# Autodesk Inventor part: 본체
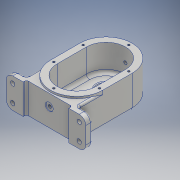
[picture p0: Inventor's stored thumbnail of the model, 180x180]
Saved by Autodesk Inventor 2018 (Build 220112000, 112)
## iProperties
Created: 2021-05
Part Number: 본체
Material: 알루미늄 6061
Document SubType Name: Modeling
Designer: Admin
Density: 2.7 g/cm^3
Appearance: 알루미늄 - 평지
Mass: 756.275 g
Surface Area: 582.942 cm^2
Volume: 280.102 cm^3
Author: Admin
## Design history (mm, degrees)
sketch "스케치1"
  geometry: L1 (-56, 0)-(56, 0) reference; L2 (0, -87.5)-(0, 87.5) reference; L3 (0, 22.5)-(0, -22.5); L4 (-40, 22.5)-(-40, -22.5); L5 (40, -22.5)-(40, 22.5); A1 r 40 centre (0, 22.5) between (40, 22.5) and (-40, 22.5); A2 r 40 centre (0, -22.5) between (-40, -22.5) and (40, -22.5); 2 further points
  constraints: 8 end point, 4 point on circle, 4 tangent, 2 centre point, 2 point on line, 1 coincident, 1 midpoint, 1 parallel
  dimensions: "d0" = 80 diameter of A2; "d1" = 45 distance of L5.start L5.end
extrude "돌출1" new body sketch "스케치1" distance "d2" = 49; taper "d3" = 0 deg
node "작업 평면1"
sketch "스케치2"
  geometry: L1 (61, -3)-(-61, -3); L2 (-61, -3)-(-61, -49); L3 (-61, -49)-(61, -49); L4 (61, -49)-(61, -3); L5 (-40, -49)-(40, -49) reference; L6 (85.4, 0)-(-85.4, 0) reference; L7 (0, -58.8)-(0, 9.8) reference; L8 (40, 0)-(-40, 0) reference; 2 further points
  constraints: 8 end point, 2 midpoint, 2 parallel, 1 horizontal, 1 perpendicular, 1 other
  dimensions: "d5" = 46 distance of L3.end L1.start; "d6" = 122 distance of L1.start L1.end
extrude "돌출2" join sketch "스케치2" distance "d7" = 10; taper "d8" = 0 deg
sketch "스케치3"
  geometry: L1 (-61, 3)-(61, 3) reference; L2 (-61, 49)-(-61, 3) reference; L3 (61, 49)-(-61, 49) reference; L4 (61, 3)-(61, 49) reference; L5 (0, 58.8)-(0, -9.8) reference; L6 (61, 49)-(-61, 49) reference; L7 (-40, 3)-(40, 3); L8 (40, 3)-(40, 49); L9 (40, 49)-(-40, 49); L10 (-40, 49)-(-40, 3); 1 further point
  constraints: 8 end point, 2 parallel, 2 point on line, 1 horizontal, 1 perpendicular, 1 other
  dimensions: "d9" = 80 distance between parallel lines of L8 L10
extrude "돌출3" join sketch "스케치3" distance "d10" = 37; taper "d11" = 0 deg
sketch "스케치4"
  geometry: L1 (-40, 22.5)-(-40, -22.5) reference; L2 (40, -22.5)-(40, 22.5) reference; L3 (0, 22.5)-(0, -22.5); L4 (-30, 22.5)-(-30, -22.5); L5 (30, -22.5)-(30, 22.5); A1 r 40 centre (0, -22.5) between (-40, -22.5) and (40, -22.5) reference; A2 r 40 centre (0, 22.5) between (40, 22.5) and (-40, 22.5) reference; A3 r 30 centre (0, 22.5) between (30, 22.5) and (-30, 22.5); A4 r 30 centre (0, -22.5) between (-30, -22.5) and (30, -22.5); 2 further points
  constraints: 8 end point, 4 point on circle, 4 tangent, 2 centre point, 1 midpoint, 1 parallel, 1 vertical
  dimensions: "d12" = 60 diameter of A4
extrude "돌출4" cut sketch "스케치4" distance "d13" = 41; taper "d14" = 0 deg
sketch "스케치5"
  geometry: L1 (-30, -22.5)-(-30, 22.5) reference; L2 (30, 22.5)-(30, -22.5) reference; C1 r 14 at (0, 22.5); C2 r 14 at (0, -22.5); A1 r 30 centre (0, -22.5) between (-30, -22.5) and (30, -22.5) reference; A2 r 30 centre (0, 22.5) between (30, 22.5) and (-30, 22.5) reference; 1 further point
  constraints: 2 centre point, 2 coincident
  dimensions: "d15" = 28 diameter of C1; "d16" = 28 diameter of C2
  node "투영된 루프3"
sketch "스케치6"
  geometry: L1 (40, -59.5)-(40, 22.5) reference; L2 (-40, 22.5)-(-40, -59.5) reference; L3 (-61, -59.5)-(-40, -59.5) reference; L4 (-61, -69.5)-(-61, -59.5) reference; L5 (-61, -69.5)-(61, -69.5) reference; L6 (61, -69.5)-(61, -59.5) reference; L7 (40, -59.5)-(61, -59.5) reference; L8 (85.4, 0)-(-85.4, 0) reference; L9 (0, -95.9)-(0, 88.9) reference; L10 (0, 22.5)-(0, -22.5); L11 (26, -22.5)-(26, -7.5); L12 (-26, -7.5)-(26, -7.5); L13 (-26, -7.5)-(-26, -22.5); A1 r 40 centre (0, 22.5) between (40, 22.5) and (-40, 22.5) reference; A2 r 26 centre (0, -22.5) between (-26, -22.5) and (26, -22.5); 2 further points
  constraints: 10 end point, 2 point on circle, 2 point on line, 2 tangent, 1 centre point, 1 coincident, 1 horizontal, 1 midpoint, 1 parallel
  dimensions: "d17" = 52 diameter of A2; "d19" = 30 distance from line of L12 A1.centre; "d20" = 47 distance from line of L5 L10.end; "d21" = 15 distance of L12.start L13.end
extrude "돌출5" join sketch "스케치6" distance "d22" = 11; taper "d23" = 0 deg
sketch "스케치7"
  geometry: L1 (-26, -22.5)-(-26, -7.5) reference; L2 (-26, -7.5)-(26, -7.5) reference; L3 (26, -7.5)-(26, -22.5) reference; L4 (40, -59.5)-(40, 22.5) reference; L5 (-40, 22.5)-(-40, -59.5) reference; L6 (-61, -59.5)-(-40, -59.5) reference; L7 (-61, -69.5)-(-61, -59.5) reference; L8 (-61, -69.5)-(61, -69.5) reference; L9 (61, -69.5)-(61, -59.5) reference; L10 (40, -59.5)-(61, -59.5) reference; L11 (85.4, 0)-(-85.4, 0) reference; L12 (0, -95.9)-(0, 88.9) reference; L13 (0, 22.5)-(0, -22.5); L14 (-26, 22.5)-(-26, -22.5); L15 (26, -22.5)-(26, 22.5); A1 r 26 centre (0, -22.5) between (-26, -22.5) and (26, -22.5) reference; A2 r 40 centre (0, 22.5) between (40, 22.5) and (-40, 22.5) reference; A3 r 26 centre (0, 22.5) between (26, 22.5) and (-26, 22.5); A4 r 26 centre (0, -22.5) between (-26, -22.5) and (26, -22.5); 2 further points
  constraints: 8 end point, 4 point on circle, 4 tangent, 2 centre point, 1 collinear, 1 midpoint, 1 parallel
  dimensions: "d24" = 52 diameter of A4
extrude "돌출6" join sketch "스케치7" distance "d25" = 8; taper "d26" = 0 deg
extrude "돌출7" cut sketch "스케치5" distance "d27" = 8; taper "d28" = 0 deg
sketch "스케치8"
  geometry: L1 (26, -7.5)-(-26, -7.5) reference; L2 (26, -7.5)-(26, 22.5) reference; L3 (-26, 22.5)-(-26, -7.5) reference; C1 r 14 at (0, 22.5); A1 r 26 centre (0, 22.5) between (26, 22.5) and (-26, 22.5) reference; 1 further point
  constraints: 1 centre point, 1 coincident
  dimensions: "d29" = 28 diameter of C1
extrude "돌출8" cut sketch "스케치8" distance "d30" = 4; taper "d31" = 0 deg
sketch "스케치9"
  geometry: C1 r 14 at (0, 0) reference; C2 r 11 at (0, 0); 1 further point
  constraints: 1 centre point, 1 coincident
  dimensions: "d32" = 22 diameter of C2
extrude "돌출9" cut sketch "스케치9" stored distance "d33" = 4; taper "d34" = 0 deg
sketch "스케치10"
  geometry: C1 r 14 at (0, 0) reference; C2 r 10 at (0, 0); 1 further point
  constraints: 1 centre point, 1 coincident
  dimensions: "d35" = 20 diameter of C2
extrude "돌출10" cut sketch "스케치10" distance "d36" = 4; taper "d37" = 0 deg
node "작업 평면2"
sketch "스케치11"
  geometry: L1 (0, -72)-(0, 12) reference; L2 (40, 0)-(-40, 0) reference; C1 r 6 at (0, -21); 1 further point
  constraints: 1 centre point, 1 point on line
  dimensions: "d39" = 12 diameter of C1; "d40" = 21 distance from line of L2 C1.centre
extrude "돌출11" join sketch "스케치11" stored distance "d41" = 4; taper "d42" = 0 deg
sketch "스케치12"
  geometry: L1 (-30, -22.5)-(-30, 22.5) reference; L2 (30, 22.5)-(30, -22.5) reference; L3 (-40, 22.5)-(-40, -22.5) reference; L4 (40, -22.5)-(40, 22.5) reference; L5 (-85.4, 0)-(85.4, 0) reference; L6 (0, -96.5)-(0, 92.5) reference; L7 (0, 22.5)-(0, -22.5); L8 (-35, 22.5)-(-35, -22.5); L9 (35, -22.5)-(35, 22.5); A1 r 30 centre (0, -22.5) between (-30, -22.5) and (30, -22.5) reference; A2 r 30 centre (0, 22.5) between (30, 22.5) and (-30, 22.5) reference; A3 r 40 centre (0, -22.5) between (-40, -22.5) and (40, -22.5) reference; A4 r 40 centre (0, 22.5) between (40, 22.5) and (-40, 22.5) reference; A5 r 35 centre (0, 22.5) between (35, 22.5) and (-35, 22.5); A6 r 35 centre (0, -22.5) between (-35, -22.5) and (35, -22.5); 8 further points
  constraints: 8 end point, 6 point on circle, 4 coincident, 4 tangent, 2 centre point, 1 collinear, 1 midpoint, 1 parallel
  dimensions: "d43" = 70 diameter of A6
hole "구멍1" sketch "스케치12" at (0, 57.5), (0, -57.5), (-35, 22.5), (35, 22.5), (35, -22.5), (-35, -22.5) diameter "d44" = 3.242; stored, may be unused: countersink angle "d48" = 90 deg, drill point angle "d50" = 118 deg; dims "d45" = 8, "d46" = 4, "d47" = 2, "d49" = 10
fillet "모깎기1" dims "d51" = 10, "d79" = 5, "d80" = 3, "d96" = 0.3
sketch "스케치13"
  geometry: L1 (-61, 39)-(-61, 13) reference; L2 (-51, 3)-(-40, 3) reference; L3 (-40, 3)-(-40, 49) reference; L4 (-40, 49)-(-51, 49) reference; L5 (51, 49)-(40, 49) reference; L6 (40, 49)-(40, 3) reference; L7 (40, 3)-(51, 3) reference; L8 (61, 13)-(61, 39) reference; C1 r 5.5 at (-51, 13); C2 r 5.5 at (-51, 39); C3 r 5.5 at (51, 13); C4 r 5.5 at (51, 39); A1 r 10 centre (-51, 39) between (-51, 49) and (-61, 39) reference; A2 r 10 centre (-51, 13) between (-61, 13) and (-51, 3) reference; A3 r 10 centre (51, 39) between (61, 39) and (51, 49) reference; A4 r 10 centre (51, 13) between (51, 3) and (61, 13) reference; 1 further point
  constraints: 4 centre point, 4 coincident
  dimensions: "d52" = 11 diameter of C1; "d53" = 11 diameter of C2; "d54" = 11 diameter of C3; "d55" = 11 diameter of C4
extrude "돌출12" cut sketch "스케치13" distance "d56" = 2; taper "d57" = 0 deg
sketch "스케치14"
  geometry: C1 r 5.5 at (0, 0) reference; C2 r 5.5 at (0, 26) reference; C3 r 5.5 at (102, 26) reference; C4 r 5.5 at (102, 0) reference; C5 r 3.3 at (0, 0); C6 r 3.3 at (0, 26); C7 r 3.3 at (102, 0); C8 r 3.3 at (102, 26); 1 further point
  constraints: 4 centre point, 4 coincident
  dimensions: "d58" = 6.6 diameter of C5; "d59" = 6.6 diameter of C6; "d60" = 6.6 diameter of C7; "d61" = 6.6 diameter of C8
extrude "돌출13" cut sketch "스케치14" stored distance "d62" = 0; taper "d63" = 0 deg
chamfer "모따기1" distance "d76" = 1; stored, may be unused: second distance "d77" = 2, angle "d78" = 45 deg
sketch "스케치18"
  geometry: L1 (0, -96.506)-(0, 92.534) reference; L2 (51, -62.5)-(51, -69.5) reference; L3 (43, -62.5)-(51, -62.5) reference; L4 (37, 22.5)-(37, -56.5) reference; L5 (-37, -56.5)-(-37, 22.5) reference; L6 (-51, -62.5)-(-43, -62.5) reference; L7 (-51, -69.5)-(-51, -62.5) reference; L8 (-51, -69.5)-(51, -69.5) reference; L9 (29, -22.5)-(29, 22.5) reference; L10 (-29, 22.5)-(-29, -22.5) reference; L11 (-51, -69.5)-(51, -69.5) reference; L12 (-35, -69.5)-(35, -69.5); L13 (35, -69.5)-(35, -64.5); L14 (35, -64.5)-(-35, -64.5); L15 (-35, -64.5)-(-35, -69.5); A1 r 37 centre (0, 22.5) between (37, 22.5) and (-37, 22.5) reference; A2 r 29 centre (0, -22.5) between (-29, -22.5) and (29, -22.5) reference; A3 r 29 centre (0, 22.5) between (29, 22.5) and (-29, 22.5) reference; A4 r 6 centre (43, -56.5) between (37, -56.5) and (43, -62.5) reference; A5 r 6 centre (-43, -56.5) between (-43, -62.5) and (-37, -56.5) reference; 1 further point
  constraints: 8 end point, 2 parallel, 1 horizontal, 1 perpendicular, 1 point on line, 1 other
  dimensions: "d81" = 5 distance between parallel lines of L12 L14; "d82" = 70 distance between parallel lines of L15 L13
extrude "돌출15" cut sketch "스케치18" stored distance "d83" = 1; taper "d84" = 0 deg
sketch "스케치19"
  geometry: L1 (0, 46)-(70, 46) reference; L2 (0, 0)-(0, 46) reference; L3 (70, 0)-(0, 0) reference; L4 (70, 0)-(70, 46) reference; L5 (75, 49)-(-5, 49) reference; L6 (35, -23)-(35, 61) reference; C1 r 6 at (35, 28); 1 further point
  constraints: 1 centre point, 1 point on line
  dimensions: "d85" = 12 diameter of C1; "d86" = 21 distance from line of L5 C1.centre
extrude "돌출16" cut sketch "스케치19" distance "d87" = 1; taper "d88" = 0 deg
sketch "스케치20"
  geometry: C1 r 6 at (0, 0) reference; 2 further points
  constraints: 1 coincident
hole "구멍3" sketch "스케치20" at (0, 0) diameter "d89" = 4.917; stored, may be unused: countersink angle "d93" = 90 deg, drill point angle "d95" = 118 deg; dims "d90" = 140, "d91" = 4, "d92" = 2, "d94" = 140
sketch "스케치21" dims "d97" = 40
  geometry: L1 (26, -7.5)-(-26, -7.5) reference; L2 (26, -7.5)-(26, 22.5) reference; L3 (-26, 22.5)-(-26, -7.5) reference; L4 (0, -96.506)-(0, 92.534) reference; C1 r 15 at (0, 22.5) reference; A1 r 26 centre (0, 22.5) between (26, 22.5) and (-26, 22.5) reference; 3 further points
  constraints: 1 coincident, 1 point on line, 1 vertical alignment, 2 other
hole "구멍4" sketch "스케치21" at (0, 42.5) diameter "d98" = 3.242; stored, may be unused: countersink angle "d102" = 90 deg, drill point angle "d104" = 118 deg; dims "d99" = 8, "d100" = 4, "d101" = 2, "d103" = 10
sketch "스케치22"
  geometry: L1 (0, -96.506)-(0, 92.534) reference; L2 (-51, -69.5)-(-35, -69.5) reference; 2 further points
  constraints: 1 point on line, 1 other
  dimensions: "d108" = 12 distance from line of L2 point (0, -57.5)
feature "엠보싱1" sketch "스케치22" dims "d109" = 0.5, "d110" = 0
fillet "모깎기2" dims "d111" = 3
node "솔리드1"
pattern_circular "원형 패턴1" dims angle "d106" = 360 deg
node "투영된 루프1"
node "투영된 루프2"
node "투영된 루프4"
node "투영된 루프5"
node "투영된 루프6"
node "투영된 루프7"
node "투영된 루프8"
node "투영된 루프9"
node "투영된 루프10"
node "투영된 루프11"
node "투영된 루프13"
node "투영된 루프14"
node "투영된 루프15"
other parameters: "d4" = -69.5, "d38" = 65.5
